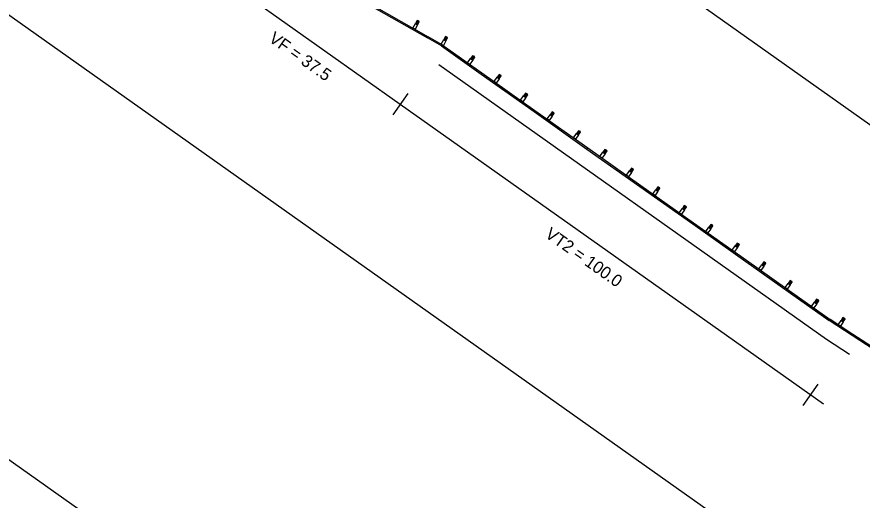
# Model space of a CAD drawing. Extents: x 16457860 to 16462445, y 6896068 to 6900243.
# Drawn here: x 16462196.7 to 16462359.6, y 6897947.5 to 6898040.5 of the extents above; entities that cross this region are included whole.
import ezdxf

# ---------------------------------------------------------------- set-up
doc = ezdxf.new("R2010")
doc.units = 0
for name, color, linetype in [('Cell', 7, 'Continuous'), ('Draft_DNC', 7, 'Continuous'), ('dsnStdLineWork', 7, 'Continuous')]:
    doc.layers.add(name, color=color, linetype=linetype)

msp = doc.modelspace()

# ---------------------------------------------------------------- linework, layer by layer
at = {"layer": 'Cell'}
for p, q in [((16462264.93, 6898042.65), (16462275.81, 6898036.49)), ((16462265.07, 6898042.88), (16462275.94, 6898036.72)), ((16462273.01, 6898038.39), (16462273.5, 6898039.26)), ((16462273.93, 6898039.01), (16462273.44, 6898038.14)), ((16462274.26, 6898039.59), (16462273.5, 6898039.26)), ((16462273.5, 6898039.26), (16462273.93, 6898039.01)), ((16462273.72, 6898039.13), (16462274.04, 6898039.71)), ((16462273.83, 6898039.84), (16462273.93, 6898039.01)), ((16462274.09, 6898039.8), (16462274.1, 6898039.8)), ((16462273.44, 6898038.14), (16462273.01, 6898038.39)), ((16462275.81, 6898036.49), (16462275.94, 6898036.72)), ((16462275.81, 6898036.49), (16462275.94, 6898036.72)), ((16462278.53, 6898034.95), (16462275.81, 6898036.49)), ((16462278.68, 6898035.17), (16462275.94, 6898036.72)), ((16462278.47, 6898035.29), (16462278.96, 6898036.16)), ((16462279.39, 6898035.91), (16462278.9, 6898035.04)), ((16462279.72, 6898036.49), (16462278.96, 6898036.16)), ((16462278.96, 6898036.16), (16462279.39, 6898035.91)), ((16462279.18, 6898036.04), (16462278.96, 6898036.16)), ((16462279.18, 6898036.04), (16462278.96, 6898036.16)), ((16462279.18, 6898036.04), (16462279.51, 6898036.62)), ((16462279.29, 6898036.74), (16462279.39, 6898035.91)), ((16462279.55, 6898036.7), (16462279.56, 6898036.71)), ((16462278.9, 6898035.04), (16462278.47, 6898035.29)), ((16462278.53, 6898034.95), (16462286.18, 6898029.53)), ((16462278.68, 6898035.17), (16462286.34, 6898029.75)), ((16462283.58, 6898031.7), (16462284.16, 6898032.52)), ((16462284.95, 6898032.77), (16462284.16, 6898032.52)), ((16462284.16, 6898032.52), (16462284.57, 6898032.23)), ((16462284.36, 6898032.37), (16462284.75, 6898032.92)), ((16462284.54, 6898033.06), (16462284.57, 6898032.23)), ((16462284.8, 6898033), (16462284.81, 6898033)), ((16462283.99, 6898031.41), (16462283.58, 6898031.7)), ((16462284.57, 6898032.23), (16462283.99, 6898031.41)), ((16462286.18, 6898029.53), (16462286.34, 6898029.75)), ((16462286.18, 6898029.53), (16462286.34, 6898029.75)), ((16462286.18, 6898029.53), (16462296.38, 6898022.31)), ((16462286.34, 6898029.75), (16462296.54, 6898022.53)), ((16462290.06, 6898029.16), (16462289.26, 6898028.91)), ((16462289.47, 6898028.76), (16462289.85, 6898029.31)), ((16462289.65, 6898029.45), (16462289.67, 6898028.62)), ((16462289.91, 6898029.39), (16462289.91, 6898029.39)), ((16462288.68, 6898028.09), (16462289.26, 6898028.91)), ((16462289.09, 6898027.8), (16462288.68, 6898028.09)), ((16462289.67, 6898028.62), (16462289.09, 6898027.8)), ((16462289.26, 6898028.91), (16462289.67, 6898028.62)), ((16462293.79, 6898024.48), (16462294.36, 6898025.3)), ((16462294.19, 6898024.19), (16462293.79, 6898024.48)), ((16462294.77, 6898025.01), (16462294.19, 6898024.19)), ((16462295.16, 6898025.55), (16462294.36, 6898025.3)), ((16462294.36, 6898025.3), (16462294.77, 6898025.01)), ((16462294.57, 6898025.15), (16462294.95, 6898025.7)), ((16462294.75, 6898025.84), (16462294.77, 6898025.01)), ((16462295.01, 6898025.78), (16462295.01, 6898025.78)), ((16462296.38, 6898022.31), (16462296.54, 6898022.53)), ((16462296.38, 6898022.31), (16462296.54, 6898022.53)), ((16462296.38, 6898022.31), (16462306.59, 6898015.09)), ((16462296.54, 6898022.53), (16462306.75, 6898015.31)), ((16462298.89, 6898020.87), (16462299.47, 6898021.69)), ((16462299.87, 6898021.4), (16462299.3, 6898020.58)), ((16462300.26, 6898021.95), (16462299.47, 6898021.69)), ((16462299.47, 6898021.69), (16462299.87, 6898021.4)), ((16462299.67, 6898021.55), (16462300.06, 6898022.09)), ((16462299.85, 6898022.23), (16462299.87, 6898021.4)), ((16462300.11, 6898022.17), (16462300.12, 6898022.17)), ((16462299.3, 6898020.58), (16462298.89, 6898020.87)), ((16462303.99, 6898017.26), (16462304.57, 6898018.08)), ((16462304.98, 6898017.79), (16462304.4, 6898016.97)), ((16462305.36, 6898018.34), (16462304.57, 6898018.08)), ((16462304.57, 6898018.08), (16462304.98, 6898017.79)), ((16462304.77, 6898017.94), (16462305.16, 6898018.48)), ((16462304.95, 6898018.62), (16462304.98, 6898017.79)), ((16462305.21, 6898018.56), (16462305.22, 6898018.56)), ((16462304.4, 6898016.97), (16462303.99, 6898017.26)), ((16462306.59, 6898015.09), (16462306.75, 6898015.31)), ((16462306.59, 6898015.09), (16462306.75, 6898015.31)), ((16462306.59, 6898015.09), (16462316.79, 6898007.87)), ((16462306.75, 6898015.31), (16462316.95, 6898008.09)), ((16462309.09, 6898013.65), (16462309.67, 6898014.47)), ((16462310.46, 6898014.73), (16462309.67, 6898014.47)), ((16462309.67, 6898014.47), (16462310.08, 6898014.18)), ((16462309.87, 6898014.33), (16462310.26, 6898014.87)), ((16462310.06, 6898015.01), (16462310.08, 6898014.18)), ((16462310.32, 6898014.95), (16462310.32, 6898014.96)), ((16462309.5, 6898013.36), (16462309.09, 6898013.65)), ((16462310.08, 6898014.18), (16462309.5, 6898013.36)), ((16462314.98, 6898010.72), (16462315.36, 6898011.26)), ((16462315.16, 6898011.4), (16462315.18, 6898010.57)), ((16462315.42, 6898011.34), (16462315.42, 6898011.35)), ((16462314.19, 6898010.04), (16462314.77, 6898010.86)), ((16462314.6, 6898009.75), (16462314.19, 6898010.04)), ((16462315.18, 6898010.57), (16462314.6, 6898009.75)), ((16462315.57, 6898011.12), (16462314.77, 6898010.86)), ((16462314.77, 6898010.86), (16462315.18, 6898010.57)), ((16462316.79, 6898007.87), (16462316.95, 6898008.09)), ((16462316.79, 6898007.87), (16462316.95, 6898008.09)), ((16462316.95, 6898008.09), (16462327.15, 6898000.87)), ((16462316.79, 6898007.87), (16462327, 6898000.65)), ((16462319.3, 6898006.43), (16462319.88, 6898007.25)), ((16462319.71, 6898006.14), (16462319.3, 6898006.43)), ((16462320.28, 6898006.96), (16462319.71, 6898006.14)), ((16462320.67, 6898007.51), (16462319.88, 6898007.25)), ((16462319.88, 6898007.25), (16462320.28, 6898006.96)), ((16462320.08, 6898007.11), (16462320.46, 6898007.65)), ((16462320.26, 6898007.8), (16462320.28, 6898006.96)), ((16462320.52, 6898007.73), (16462320.52, 6898007.74)), ((16462324.4, 6898002.82), (16462324.98, 6898003.64)), ((16462325.39, 6898003.35), (16462324.81, 6898002.54)), ((16462325.77, 6898003.9), (16462324.98, 6898003.64)), ((16462324.98, 6898003.64), (16462325.39, 6898003.35)), ((16462325.18, 6898003.5), (16462325.57, 6898004.04)), ((16462325.36, 6898004.19), (16462325.39, 6898003.35)), ((16462325.62, 6898004.12), (16462325.63, 6898004.13)), ((16462324.81, 6898002.54), (16462324.4, 6898002.82)), ((16462327, 6898000.65), (16462327.15, 6898000.87)), ((16462327, 6898000.65), (16462327.15, 6898000.87)), ((16462327, 6898000.65), (16462337.2, 6897993.43)), ((16462327.15, 6898000.87), (16462337.36, 6897993.66)), ((16462329.5, 6897999.21), (16462330.08, 6898000.03)), ((16462330.87, 6898000.29), (16462330.08, 6898000.03)), ((16462330.08, 6898000.03), (16462330.49, 6897999.74)), ((16462330.28, 6897999.89), (16462330.67, 6898000.43)), ((16462330.46, 6898000.58), (16462330.49, 6897999.74)), ((16462330.72, 6898000.51), (16462330.73, 6898000.52)), ((16462329.91, 6897998.93), (16462329.5, 6897999.21)), ((16462330.49, 6897999.74), (16462329.91, 6897998.93)), ((16462335.98, 6897996.68), (16462335.18, 6897996.42)), ((16462335.39, 6897996.28), (16462335.77, 6897996.82)), ((16462335.57, 6897996.97), (16462335.59, 6897996.13)), ((16462335.83, 6897996.9), (16462335.83, 6897996.91)), ((16462334.6, 6897995.6), (16462335.18, 6897996.42)), ((16462335.01, 6897995.32), (16462334.6, 6897995.6)), ((16462335.59, 6897996.13), (16462335.01, 6897995.32)), ((16462335.18, 6897996.42), (16462335.59, 6897996.13)), ((16462337.2, 6897993.43), (16462337.36, 6897993.66)), ((16462337.2, 6897993.43), (16462337.36, 6897993.66)), ((16462337.2, 6897993.43), (16462347.41, 6897986.22)), ((16462337.36, 6897993.66), (16462347.56, 6897986.44)), ((16462340.67, 6897993.36), (16462340.69, 6897992.52)), ((16462340.93, 6897993.29), (16462340.93, 6897993.3)), ((16462339.71, 6897992), (16462340.28, 6897992.81)), ((16462340.11, 6897991.71), (16462339.71, 6897992)), ((16462340.69, 6897992.52), (16462340.11, 6897991.71)), ((16462341.08, 6897993.07), (16462340.28, 6897992.81)), ((16462340.28, 6897992.81), (16462340.69, 6897992.52)), ((16462340.49, 6897992.67), (16462340.87, 6897993.21)), ((16462344.81, 6897988.39), (16462345.39, 6897989.2)), ((16462345.22, 6897988.1), (16462344.81, 6897988.39)), ((16462345.79, 6897988.91), (16462345.22, 6897988.1)), ((16462346.18, 6897989.46), (16462345.39, 6897989.2)), ((16462345.39, 6897989.2), (16462345.79, 6897988.91)), ((16462345.59, 6897989.06), (16462345.98, 6897989.6)), ((16462345.77, 6897989.75), (16462345.79, 6897988.91)), ((16462346.03, 6897989.68), (16462346.04, 6897989.69)), ((16462347.41, 6897986.22), (16462347.56, 6897986.44)), ((16462347.41, 6897986.22), (16462347.56, 6897986.44)), ((16462347.41, 6897986.22), (16462353.31, 6897982.04)), ((16462347.56, 6897986.44), (16462353.46, 6897982.26)), ((16462349.91, 6897984.78), (16462350.49, 6897985.59)), ((16462350.9, 6897985.3), (16462350.32, 6897984.49)), ((16462351.28, 6897985.85), (16462350.49, 6897985.59)), ((16462350.49, 6897985.59), (16462350.9, 6897985.3)), ((16462350.69, 6897985.45), (16462351.08, 6897985.99)), ((16462350.87, 6897986.14), (16462350.9, 6897985.3)), ((16462351.13, 6897986.07), (16462351.14, 6897986.08)), ((16462350.32, 6897984.49), (16462349.91, 6897984.78)), ((16462357.74, 6897979.16), (16462353.31, 6897982.04)), ((16462357.89, 6897979.39), (16462353.46, 6897982.26)), ((16462355.06, 6897981.23), (16462355.6, 6897982.07)), ((16462356.38, 6897982.35), (16462355.6, 6897982.07)), ((16462355.6, 6897982.07), (16462356.02, 6897981.79)), ((16462355.81, 6897981.93), (16462356.17, 6897982.49)), ((16462355.96, 6897982.63), (16462356.02, 6897981.8)), ((16462356.23, 6897982.57), (16462356.23, 6897982.58)), ((16462355.48, 6897980.96), (16462355.06, 6897981.23)), ((16462356.02, 6897981.79), (16462355.48, 6897980.96)), ((16462357.89, 6897979.39), (16462357.74, 6897979.16))]:
    msp.add_line(p, q, dxfattribs=at)
for points in [[(16462273.5, 6898039.26), (16462273.93, 6898039.01), (16462274.26, 6898039.59), (16462273.83, 6898039.84)], [(16462278.96, 6898036.16), (16462279.39, 6898035.91), (16462279.72, 6898036.49), (16462279.29, 6898036.74)], [(16462284.16, 6898032.52), (16462284.57, 6898032.23), (16462284.95, 6898032.77), (16462284.54, 6898033.06)], [(16462289.26, 6898028.91), (16462289.67, 6898028.62), (16462290.06, 6898029.16), (16462289.65, 6898029.45)], [(16462294.36, 6898025.3), (16462294.77, 6898025.01), (16462295.16, 6898025.55), (16462294.75, 6898025.84)], [(16462299.47, 6898021.69), (16462299.87, 6898021.4), (16462300.26, 6898021.95), (16462299.85, 6898022.23)], [(16462304.57, 6898018.08), (16462304.98, 6898017.79), (16462305.36, 6898018.34), (16462304.95, 6898018.62)], [(16462309.67, 6898014.47), (16462310.08, 6898014.18), (16462310.46, 6898014.73), (16462310.06, 6898015.01)], [(16462314.77, 6898010.86), (16462315.18, 6898010.57), (16462315.57, 6898011.12), (16462315.16, 6898011.4)], [(16462319.88, 6898007.25), (16462320.28, 6898006.96), (16462320.67, 6898007.51), (16462320.26, 6898007.8)], [(16462324.98, 6898003.64), (16462325.39, 6898003.35), (16462325.77, 6898003.9), (16462325.36, 6898004.19)], [(16462330.08, 6898000.03), (16462330.49, 6897999.74), (16462330.87, 6898000.29), (16462330.46, 6898000.58)], [(16462335.18, 6897996.42), (16462335.59, 6897996.13), (16462335.98, 6897996.68), (16462335.57, 6897996.97)], [(16462340.28, 6897992.81), (16462340.69, 6897992.52), (16462341.08, 6897993.07), (16462340.67, 6897993.36)], [(16462345.39, 6897989.2), (16462345.79, 6897988.91), (16462346.18, 6897989.46), (16462345.77, 6897989.75)], [(16462350.49, 6897985.59), (16462350.9, 6897985.3), (16462351.28, 6897985.85), (16462350.87, 6897986.14)], [(16462355.6, 6897982.07), (16462356.02, 6897981.8), (16462356.38, 6897982.35), (16462355.96, 6897982.63)]]:
    msp.add_lwpolyline(points, close=True, dxfattribs=at)
for points in [[(16462274.02, 6898039.73), (16462274.04, 6898039.77), (16462274.1, 6898039.73), (16462274.07, 6898039.7)], [(16462274.05, 6898039.76), (16462274.08, 6898039.81), (16462274.11, 6898039.79), (16462274.08, 6898039.74)], [(16462279.48, 6898036.63), (16462279.5, 6898036.67), (16462279.56, 6898036.64), (16462279.53, 6898036.6)], [(16462279.51, 6898036.66), (16462279.54, 6898036.71), (16462279.57, 6898036.69), (16462279.54, 6898036.65)], [(16462284.72, 6898032.94), (16462284.75, 6898032.97), (16462284.8, 6898032.93), (16462284.78, 6898032.9)], [(16462284.76, 6898032.97), (16462284.79, 6898033.01), (16462284.82, 6898032.99), (16462284.79, 6898032.94)], [(16462289.82, 6898029.33), (16462289.85, 6898029.36), (16462289.9, 6898029.32), (16462289.88, 6898029.29)], [(16462289.86, 6898029.36), (16462289.89, 6898029.4), (16462289.92, 6898029.38), (16462289.89, 6898029.33)], [(16462294.93, 6898025.72), (16462294.95, 6898025.75), (16462295.01, 6898025.72), (16462294.98, 6898025.68)], [(16462294.96, 6898025.75), (16462294.99, 6898025.79), (16462295.03, 6898025.77), (16462294.99, 6898025.72)], [(16462300.03, 6898022.11), (16462300.05, 6898022.14), (16462300.11, 6898022.11), (16462300.08, 6898022.07)], [(16462300.06, 6898022.14), (16462300.1, 6898022.18), (16462300.13, 6898022.16), (16462300.1, 6898022.11)], [(16462305.13, 6898018.5), (16462305.16, 6898018.53), (16462305.21, 6898018.5), (16462305.18, 6898018.46)], [(16462305.17, 6898018.53), (16462305.2, 6898018.57), (16462305.23, 6898018.55), (16462305.2, 6898018.5)], [(16462310.23, 6898014.89), (16462310.26, 6898014.92), (16462310.31, 6898014.89), (16462310.29, 6898014.85)], [(16462310.27, 6898014.92), (16462310.3, 6898014.96), (16462310.33, 6898014.94), (16462310.3, 6898014.89)], [(16462315.33, 6898011.28), (16462315.36, 6898011.31), (16462315.41, 6898011.28), (16462315.39, 6898011.24)], [(16462315.37, 6898011.31), (16462315.4, 6898011.35), (16462315.43, 6898011.33), (16462315.4, 6898011.28)], [(16462320.44, 6898007.67), (16462320.46, 6898007.71), (16462320.52, 6898007.67), (16462320.49, 6898007.63)], [(16462320.47, 6898007.7), (16462320.5, 6898007.74), (16462320.54, 6898007.72), (16462320.51, 6898007.67)], [(16462325.54, 6898004.06), (16462325.56, 6898004.1), (16462325.62, 6898004.06), (16462325.59, 6898004.02)], [(16462325.58, 6898004.09), (16462325.61, 6898004.13), (16462325.64, 6898004.11), (16462325.61, 6898004.06)], [(16462330.64, 6898000.45), (16462330.67, 6898000.49), (16462330.72, 6898000.45), (16462330.7, 6898000.41)], [(16462330.68, 6898000.48), (16462330.71, 6898000.52), (16462330.74, 6898000.5), (16462330.71, 6898000.46)], [(16462335.74, 6897996.84), (16462335.77, 6897996.88), (16462335.82, 6897996.84), (16462335.8, 6897996.8)], [(16462335.78, 6897996.87), (16462335.81, 6897996.91), (16462335.84, 6897996.89), (16462335.81, 6897996.85)], [(16462340.85, 6897993.23), (16462340.87, 6897993.27), (16462340.93, 6897993.23), (16462340.9, 6897993.19)], [(16462340.88, 6897993.26), (16462340.91, 6897993.3), (16462340.95, 6897993.28), (16462340.91, 6897993.24)], [(16462345.95, 6897989.62), (16462345.97, 6897989.66), (16462346.03, 6897989.62), (16462346, 6897989.58)], [(16462345.98, 6897989.65), (16462346.02, 6897989.69), (16462346.05, 6897989.67), (16462346.02, 6897989.63)], [(16462351.05, 6897986.01), (16462351.08, 6897986.05), (16462351.13, 6897986.01), (16462351.1, 6897985.97)], [(16462351.09, 6897986.04), (16462351.12, 6897986.08), (16462351.15, 6897986.06), (16462351.12, 6897986.02)], [(16462356.15, 6897982.51), (16462356.17, 6897982.54), (16462356.23, 6897982.51), (16462356.2, 6897982.47)], [(16462356.18, 6897982.54), (16462356.21, 6897982.58), (16462356.24, 6897982.56), (16462356.21, 6897982.52)]]:
    msp.add_lwpolyline(points, dxfattribs=at)
at = {"layer": 'Draft_DNC'}
for p, q in [((16462240.12, 6898045.27), (16462270.58, 6898023.72)), ((16462272.03, 6898025.76), (16462269.14, 6898021.68)), ((16462270.58, 6898023.72), (16462352.2, 6897965.98)), ((16462351.12, 6897969.8), (16462348.23, 6897965.72))]:
    msp.add_line(p, q, dxfattribs=at)
for points in [[(16462202.58, 6898132.04), (16462444.86, 6897960.63), (16462399.4, 6897896.38), (16462157.12, 6898067.79)], [(16462116.71, 6898010.67), (16462358.99, 6897839.26), (16462313.53, 6897775.01), (16462071.25, 6897946.41)]]:
    msp.add_lwpolyline(points, close=True, dxfattribs=at)
msp.add_lwpolyline([(16462278.01, 6898031.35), (16462352.79, 6897978.45), (16462357.23, 6897975.57)], dxfattribs=at)
at = {"layer": 'dsnStdLineWork'}
for p, q in [((16462357.89, 6897979.39), (16462357.74, 6897979.16)), ((16462392.3, 6897956.73), (16462357.74, 6897979.16)), ((16462392.45, 6897956.96), (16462357.89, 6897979.39))]:
    msp.add_line(p, q, dxfattribs=at)

# ---------------------------------------------------------------- texts
at = {"layer": 'Draft_DNC'}
for s, height, p in [('VF = 37.5', 2.344, (16462245.06, 6898035.93)), ('VT2 = 100.0', 2.3437, (16462298.34, 6897998.24))]:
    msp.add_text(s, height=height, rotation=324.7216, dxfattribs=at).set_placement(p)

doc.saveas('drawing.dxf')
